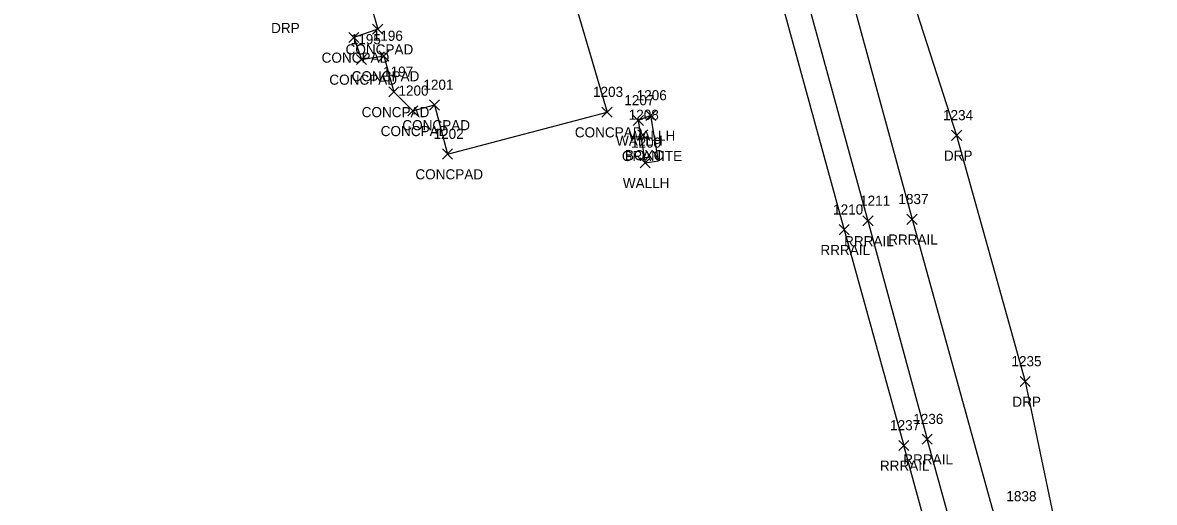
# Model space of a CAD drawing. Extents: x 1635588 to 1637550, y 621583 to 623638.
# Drawn here: x 1636402 to 1636625.5, y 622685.3 to 622780.1 of the extents above; entities that cross this region are included whole.
import ezdxf

# ---------------------------------------------------------------- set-up
doc = ezdxf.new("R2010")
doc.units = 0
for name, color, linetype in [('D_A', 7, 'Continuous'), ('D_C', 7, 'Continuous'), ('D_I', 7, 'Continuous'), ('D_TIC', 7, 'Continuous'), ('DHW', 7, 'Continuous'), ('L_A', 7, 'Continuous'), ('L_I', 7, 'Continuous'), ('L_TIC', 7, 'Continuous'), ('LS', 7, 'Continuous'), ('R_A', 7, 'Continuous'), ('R_I', 7, 'Continuous'), ('R_TIC', 7, 'Continuous'), ('RDP', 7, 'Continuous'), ('RR', 7, 'Continuous')]:
    doc.layers.add(name, color=color, linetype=linetype)

msp = doc.modelspace()

# ---------------------------------------------------------------- linework, layer by layer
at = {"layer": 'D_TIC'}
for points in [[(1636525.06, 622760.75), (1636527.06, 622762.75)], [(1636527.06, 622760.75), (1636525.06, 622762.75)], [(1636522.57, 622759.77), (1636524.57, 622761.77)], [(1636524.57, 622759.77), (1636522.57, 622761.77)], [(1636523.45, 622756.9), (1636525.45, 622758.9)], [(1636525.45, 622756.9), (1636523.45, 622758.9)], [(1636523.92, 622751.4), (1636525.92, 622753.4)], [(1636525.92, 622751.4), (1636523.92, 622753.4)]]:
    msp.add_lwpolyline(points, dxfattribs=at)
at = {"layer": 'DHW'}
msp.add_lwpolyline([(1636526.06, 622761.75), (1636523.57, 622760.77), (1636524.92, 622752.4), (1636527.56, 622752.82), (1636526.06, 622761.75)], dxfattribs=at)
at = {"layer": 'L_TIC'}
for points in [[(1636466.38, 622776.17), (1636468.38, 622778.17)], [(1636468.38, 622776.17), (1636466.38, 622778.17)], [(1636471.1, 622777.8), (1636473.1, 622779.8)], [(1636473.1, 622777.8), (1636471.1, 622779.8)], [(1636467.89, 622771.82), (1636469.89, 622773.82)], [(1636469.89, 622771.82), (1636467.89, 622773.82)], [(1636472.3, 622772.5), (1636474.3, 622774.5)], [(1636474.3, 622772.5), (1636472.3, 622774.5)], [(1636474.29, 622765.41), (1636476.29, 622767.41)], [(1636476.29, 622765.41), (1636474.29, 622767.41)], [(1636482.31, 622762.83), (1636484.31, 622764.83)], [(1636484.31, 622762.83), (1636482.31, 622764.83)], [(1636478.04, 622761.67), (1636480.04, 622763.67)], [(1636480.04, 622761.67), (1636478.04, 622763.67)], [(1636516.39, 622761.42), (1636518.39, 622763.42)], [(1636518.39, 622761.42), (1636516.39, 622763.42)], [(1636484.9, 622753.13), (1636486.9, 622755.13)], [(1636486.9, 622753.13), (1636484.9, 622755.13)]]:
    msp.add_lwpolyline(points, dxfattribs=at)
at = {"layer": 'LS'}
for points in [[(1636509.35, 622790.02), (1636517.39, 622762.42)], [(1636469.62, 622787.52), (1636472.1, 622778.8), (1636467.38, 622777.17), (1636468.89, 622772.82), (1636473.3, 622773.5), (1636475.29, 622766.41), (1636479.04, 622762.67), (1636483.31, 622763.83), (1636485.9, 622754.13), (1636517.39, 622762.42)]]:
    msp.add_lwpolyline(points, dxfattribs=at)
at = {"layer": 'R_TIC'}
for points in [[(1636585.44, 622756.82), (1636587.44, 622758.82)], [(1636587.44, 622756.82), (1636585.44, 622758.82)], [(1636576.63, 622740.25), (1636578.63, 622742.25)], [(1636578.63, 622740.25), (1636576.63, 622742.25)], [(1636563.25, 622738.19), (1636565.25, 622740.19)], [(1636565.25, 622738.19), (1636563.25, 622740.19)], [(1636567.93, 622739.93), (1636569.93, 622741.93)], [(1636569.93, 622739.93), (1636567.93, 622741.93)], [(1636598.97, 622708.22), (1636600.97, 622710.22)], [(1636600.97, 622708.22), (1636598.97, 622710.22)], [(1636575, 622695.58), (1636577, 622697.58)], [(1636577, 622695.58), (1636575, 622697.58)], [(1636579.62, 622696.82), (1636581.62, 622698.82)], [(1636581.62, 622696.82), (1636579.62, 622698.82)]]:
    msp.add_lwpolyline(points, dxfattribs=at)
at = {"layer": 'RDP'}
msp.add_lwpolyline([(1636570.79, 622806.25), (1636586.44, 622757.82), (1636599.97, 622709.22), (1636612.89, 622647.59)], dxfattribs=at)
at = {"layer": 'RR'}
for points in [[(1636406.43, 623208.62), (1636424.65, 623171.19), (1636442.27, 623131.47), (1636462.36, 623079.17), (1636475.1, 623045.34), (1636499.5, 622979.8), (1636509.41, 622950.55), (1636516.07, 622929.71), (1636530.2, 622882.11), (1636568.93, 622740.93), (1636580.62, 622697.82)], [(1636401.96, 623205.78), (1636420.49, 623168.36), (1636437.73, 623129.25), (1636458.96, 623074.5), (1636470.76, 623043.73), (1636495.27, 622977.34), (1636504.04, 622950.72), (1636511.18, 622928.71), (1636525.38, 622880.65), (1636564.25, 622739.19), (1636576, 622696.58)], [(1636548.94, 622846.43), (1636558.8, 622810.29), (1636577.63, 622741.25), (1636594.59, 622680.12), (1636616.94, 622598.07), (1636625.5, 622566.08)], [(1636595.36, 622644.51), (1636580.62, 622697.82)], [(1636590.62, 622643.06), (1636576, 622696.58)]]:
    msp.add_lwpolyline(points, dxfattribs=at)

# ---------------------------------------------------------------- texts
at = {"layer": 'D_A'}
for s, p in [('WALLH', (1636519.16, 622755.77)), ('WALLH', (1636521.65, 622756.75)), ('BOXC', (1636520.94, 622752.9)), ('WALLH', (1636520.51, 622747.4))]:
    msp.add_text(s, height=2, dxfattribs=at).set_placement(p)
at = {"layer": 'D_C'}
msp.add_text('GRANITE', height=2, dxfattribs=at).set_placement((1636520.33, 622752.75))
at = {"layer": 'D_I'}
for s, p in [('1206', (1636523.24, 622764.75)), ('1207', (1636520.8, 622763.77)), ('1208', (1636521.67, 622760.9)), ('1209', (1636522.14, 622755.4))]:
    msp.add_text(s, height=2, dxfattribs=at).set_placement(p)
at = {"layer": 'L_A'}
for p in [(1636465.75, 622773.8), (1636461.02, 622772.17), (1636462.54, 622767.82), (1636466.95, 622768.5), (1636468.93, 622761.41), (1636476.96, 622758.83), (1636472.69, 622757.67), (1636511.03, 622757.42), (1636479.54, 622749.13)]:
    msp.add_text('CONCPAD', height=2, dxfattribs=at).set_placement(p)
at = {"layer": 'L_I'}
for s, p in [('1195', (1636466.77, 622775.82)), ('1196', (1636471.12, 622776.5)), ('1197', (1636473.16, 622769.41)), ('1200', (1636476.19, 622765.67)), ('1201', (1636481.11, 622766.83)), ('1203', (1636514.62, 622765.42)), ('1202', (1636483.13, 622757.13))]:
    msp.add_text(s, height=2, dxfattribs=at).set_placement(p)
at = {"layer": 'R_A'}
for s, p in [('DRP', (1636451.04, 622778.03)), ('DRP', (1636583.93, 622752.82)), ('RRRAIL', (1636564.22, 622735.93)), ('RRRAIL', (1636572.92, 622736.25)), ('RRRAIL', (1636559.54, 622734.19)), ('DRP', (1636597.45, 622704.22)), ('RRRAIL', (1636571.29, 622691.58)), ('RRRAIL', (1636575.91, 622692.82))]:
    msp.add_text(s, height=2, dxfattribs=at).set_placement(p)
at = {"layer": 'R_I'}
for s, p in [('1234', (1636583.75, 622760.82)), ('1211', (1636567.37, 622743.93)), ('1837', (1636574.94, 622744.25)), ('1210', (1636562.04, 622742.19)), ('1235', (1636597.27, 622712.22)), ('1236', (1636577.87, 622700.82)), ('1237', (1636573.3, 622699.58)), ('1838', (1636596.27, 622685.56))]:
    msp.add_text(s, height=2, dxfattribs=at).set_placement(p)

doc.saveas('drawing.dxf')
